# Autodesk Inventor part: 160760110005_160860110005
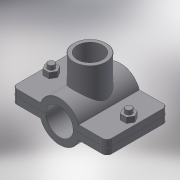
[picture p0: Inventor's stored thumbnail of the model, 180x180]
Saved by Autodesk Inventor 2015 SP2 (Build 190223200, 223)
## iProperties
Created: 2017-05
Part Number: 160760110005_160860110005
Material: Generic
Description: PLASSON SADDLE 110-1/2"
Document SubType Name: Modeling
Designer: KIM
Density: 1 g/cm^3
Appearance: Default
Author: KIM
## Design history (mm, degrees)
derived "16076.ipt"
feature "Solid1::16076.ipt"
feature "Solid2::16076.ipt"
tag "TaggingFeature1"
body "Solid1"
other parameters: "d0" = 121, "d1" = 165, "d2" = 55, "d4" = 116, "d5" = 0, "d6" = 8.25, "d7" = 165, "d8" = 0.1, "d10" = 0, "d11" = 1.1, "d14" = 24.2203, "d20" = 1.1, "d23" = 1.1, "d36" = 13, "d37" = 10.4, "d38" = 63, "d39" = 0, "d40" = 3, "d41" = 5, "d42" = 0, "d43" = 8, "d44" = 3, "d45" = 0, "d46" = 1.1, "d51" = 83, "d52" = 18.631, "d53" = 18, "d54" = 0, "d55" = 16, "d57" = 0, "d58" = 118.8, "d60" = 0, "d62" = 13, "d63" = 10.4, "d66" = 95.2, "B_" = 16, "G_" = 18.631, "A_" = 83, "L_" = 165, "L_1" = 116, "l_2" = 18
